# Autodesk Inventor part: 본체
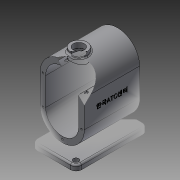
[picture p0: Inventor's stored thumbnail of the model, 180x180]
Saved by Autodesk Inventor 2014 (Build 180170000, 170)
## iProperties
Created: 2016-12
Part Number: 본체
Material: 일반
Document SubType Name: Modeling
Designer: mduedu
Density: 1 g/cm^3
Appearance: 기본값
Author: mduedu
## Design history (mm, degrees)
sketch "스케치1"
  geometry: L1 (40, -25)-(40, 25); L2 (-40, 25)-(-40, -25); L3 (-40, -25)-(40, 25); L4 (40, -25)-(-40, 25); L5 (0, 25)-(0, -25); A1 r 40 centre (0, 25) between (40, 25) and (-40, 25); A2 r 40 centre (0, -25) between (-40, -25) and (40, -25); 1 further point
  constraints: 10 end point, 4 point on circle, 3 tangent, 2 centre point, 2 midpoint, 2 parallel, 1 vertical
  dimensions: "d0" = 130 dimension on A2 A1; "d2" = 80 distance between parallel lines of L1 L2
extrude "돌출1" new body sketch "스케치1" stored distance "d3" = 100; taper "d4" = 0 deg
feature "쉘1" dims "d5" = 10
sketch "스케치2"
  geometry: L1 (-75, 65)-(-85, 65); L2 (-85, 65)-(-85, -65); L3 (-85, -65)-(-75, -65); L4 (-75, -65)-(-75, 65); 2 further points
  constraints: 8 end point, 2 parallel, 1 horizontal, 1 horizontal alignment, 1 midpoint, 1 perpendicular
  dimensions: "d6" = 85 distance from line of L2 point (0, 0); "d7" = 130 distance of L1.end L2.end; "d8" = 10 distance of L2.end L3.end
extrude "돌출2" join sketch "스케치2" stored distance "d9" = 80; taper "d10" = 0 deg
fillet "모깎기1" dims "d11" = 10
sketch "스케치3"
  geometry: L1 (-10, 10)-(-10, 120) reference; L2 (60, 0)-(0, 0) reference; L3 (70, 120)-(70, 10) reference; L4 (0, 130)-(60, 130) reference; A1 r 10 centre (0, 120) between (0, 130) and (-10, 120) reference; A2 r 10 centre (0, 10) between (-10, 10) and (0, 0) reference; A3 r 10 centre (60, 10) between (60, 0) and (70, 10) reference; A4 r 10 centre (60, 120) between (70, 120) and (60, 130) reference; 5 further points
  constraints: 4 coincident
hole "구멍1" sketch "스케치3" at (60, 120), (60, 10), (0, 10), (0, 120) diameter "d12" = 10; stored, may be unused: countersink angle "d16" = 90 deg, drill point angle "d18" = 118 deg; dims "d13" = 6, "d14" = 4, "d15" = 2, "d17" = 8
sketch "스케치5"
  geometry: L1 (34, 35)-(26, 35); L2 (26, 35)-(26, 95); L3 (26, 95)-(34, 95); L4 (34, 95)-(34, 35); L5 (34, 35)-(26, 95); L6 (26, 35)-(34, 95); 1 further point
  constraints: 12 end point, 2 midpoint, 2 parallel, 1 horizontal, 1 perpendicular
  dimensions: "d22" = 8 distance of L2.end L3.end; "d24" = 60 distance of L1.end L2.end
extrude "돌출3" join sketch "스케치5" stored distance "d25" = 80; taper "d26" = 0 deg
feature "면 기울기1" dims angle "d27" = 5 deg
sketch "스케치6"
  geometry: L1 (-30, -75)-(30, -75) reference; L2 (-17.524, -60.957)-(-20, -75); A1 r 40 centre (0, -25) between (-40, -25) and (40, -25) reference; 1 further point
  constraints: 2 end point, 1 point on circle, 1 point on line
  dimensions: "d28" = 20 horizontal distance of A1.centre L2.end; "d29" = 80 deg angle of L2 L1
feature "리브1" sketch "스케치6" dims "d30" = 1, "d31" = 8, "d32" = 0, "d33" = 0, "d34" = 1, "d35" = 1
fillet "모깎기2" dims "d36" = 3
fillet "모깎기3" dims "d37" = 3, "d38" = 3
node "작업 평면1"
sketch "스케치9"
  geometry: 1 further point
sketch "스케치7"
  geometry: L1 (40, 50)-(-40, 50) reference; C1 r 15 at (0, 20); 1 further point
  constraints: 1 centre point, 1 vertical alignment
  dimensions: "d40" = 30 diameter of C1; "d41" = 30 distance from line of C1.centre L1
extrude "돌출4" join sketch "스케치7" stored distance "d42" = 80; taper "d43" = 0 deg
hole "구멍2" diameter "d46" = 20; stored, may be unused: countersink angle "d50" = 90 deg, drill point angle "d52" = 118 deg; dims "d44" = 10, "d45" = 10, "d47" = 6, "d48" = 4, "d49" = 2, "d51" = 8
fillet "모깎기4" dims "d53" = 3
node "작업 평면2"
sketch "스케치8"
  geometry: C1 r 15 at (0, 0) reference; C2 r 15 at (0, 0); 1 further point
  constraints: 1 centre point, 1 coincident
  dimensions: "d55" = 30 diameter of C2
extrude "돌출5" cut sketch "스케치8" stored distance "d56" = 80; taper "d57" = 0 deg
chamfer "모따기1" distance "d58" = 1; stored, may be unused: second distance "d59" = 2, angle "d60" = 45 deg
sketch "스케치10"
  geometry: 2 further points
  constraints: 1 coincident, 1 other
feature "엠보싱1" sketch "스케치10" dims "d0" = 130, "d2" = 80, "d61" = 0.5, "d62" = 0
sketch "스케치11"
  geometry: 1 further point
hole "구멍3" sketch "스케치11" at (0, 60) diameter "d63" = 3.242; stored, may be unused: countersink angle "d67" = 90 deg, drill point angle "d69" = 120 deg; dims "d64" = 8.6, "d65" = 4, "d66" = 2, "d68" = 10.6
sketch "스케치12"
  geometry: 1 further point
hole "구멍5" sketch "스케치12" at (0, 60) diameter "d70" = 3.242; stored, may be unused: countersink angle "d74" = 90 deg, drill point angle "d76" = 120 deg; dims "d71" = 8.6, "d72" = 4, "d73" = 2, "d75" = 10.6
node "솔리드1"
mirror "대칭1"
pattern_linear "직사각형 패턴1"
pattern_linear "직사각형 패턴2"
node "투영된 루프1"
sketch "스케치13"
  geometry: L1 (-40, 25)-(-40, -25) reference; L2 (40, -25)-(40, 25) reference; L3 (35, 25)-(35, -25); L4 (-35, -25)-(-35, 25); A1 r 40 centre (0, 25) between (40, 25) and (-40, 25) reference; A2 r 40 centre (0, -25) between (-40, -25) and (40, -25) reference; A3 r 35 centre (0, 25) between (35, 25) and (-35, 25); A4 r 35 centre (0, -25) between (-35, -25) and (35, -25); 2 further points
  constraints: 5 point on circle, 4 end point, 2 centre point, 3 other
  dimensions: "d77" = 5 distance between parallel lines of L3 L2
sketch "스케치14"
  geometry: L1 (-40, 25)-(-40, -25) reference; L2 (40, -25)-(40, 25) reference; L3 (35, 25)-(35, -25); L4 (-35, -25)-(-35, 25); A1 r 40 centre (0, 25) between (40, 25) and (-40, 25) reference; A2 r 40 centre (0, -25) between (-40, -25) and (40, -25) reference; A3 r 35 centre (0, 25) between (35, 25) and (-35, 25); A4 r 35 centre (0, -25) between (-35, -25) and (35, -25); 2 further points
  constraints: 5 point on circle, 4 end point, 2 centre point, 3 other
  dimensions: "d80" = 5 distance between parallel lines of L2 L3
